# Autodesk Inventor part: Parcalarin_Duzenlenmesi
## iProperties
Company: Autodesk, Inc.
Shininess: 64.0
Length Units: 11269
Angle Units: 11279
Time Units: 11290
Mass Units: 11283
Length Display Precision: 3
Angle Display Precision: 2
Compacted: True
Part Number: Parcalarin_Duzenlenmesi
Document SubType Name: Modeling
Created: 2003-11
Catalog Web Link: www.autodesk.com
Vendor: Autodesk, Inc.
Designer: Administrator
Manufacturer: Standard
Standards Organization: Custom
Density: 1 g/cm^3
Density: 0.0
Volumn: 0.0
Area: 0.0
PropertySet Name: Model Information
Control State: 0
Master: False
Checked Out: False
Author: Administrator
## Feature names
1. Extrusion1
2. Extrusion2
3. Hole1
4. Extrusion3
5. Hole2
6. Hole3
7. Hole4
8. Hole5
9. Extrusion4
10. Chamfer1
